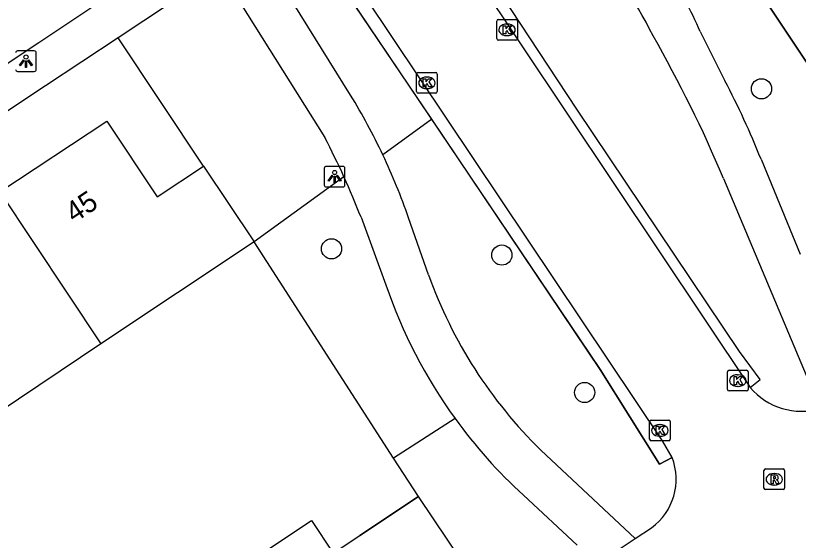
# Model space of a CAD drawing. Extents: x 158352 to 159489, y 383828 to 384597.
# Drawn here: x 158685.53 to 158723.41, y 384335.08 to 384360.5 of the extents above; entities that cross this region are included whole.
import ezdxf

# ---------------------------------------------------------------- set-up
doc = ezdxf.new("R2010")
doc.units = 0
for name, color, linetype in [('IMGEO_Boom', 7, 'Continuous'), ('IMGEO_Groenvoorziening', 7, 'Continuous'), ('IMGEO_Haag', 7, 'Continuous'), ('IMGEO_Kolk', 7, 'Continuous'), ('IMGEO_Lichtpunt', 7, 'Continuous'), ('IMGEO_Muur', 7, 'Continuous'), ('IMGEO_Pand', 7, 'Continuous'), ('IMGEO_Pand_nummerreeks', 7, 'Continuous'), ('IMGEO_Rijbaan_lokaal_open', 7, 'Continuous'), ('IMGEO_Rioolput', 7, 'Continuous'), ('IMGEO_Voetpad_gesloten', 7, 'Continuous'), ('IMGEO_Voetpad_open', 7, 'Continuous')]:
    doc.layers.add(name, color=color, linetype=linetype)

msp = doc.modelspace()

# ---------------------------------------------------------------- linework, layer by layer
at = {"layer": 'IMGEO_Boom'}
for centre in [(158721.624, 384356.956), (158700.816, 384349.204), (158709.059, 384348.902), (158713.066, 384342.244)]:
    msp.add_circle(centre, 0.489, dxfattribs=at)
at = {"layer": 'IMGEO_Groenvoorziening'}
for points in [[(158721.08, 384342.484), (158721.565, 384342.867), (158720.569, 384344.237), (158712.693, 384355.962), (158705.402, 384367.055), (158704.999, 384368.433), (158707.385, 384369.905), (158707.074, 384370.542)], [(158705.665, 384355.479), (158699.704, 384364.332), (158699.322, 384364.675), (158698.031, 384363.799), (158697.75, 384364.255)], [(158720.967, 384362.517), (158727.592, 384352.549), (158727.446, 384352.432), (158727.575, 384352.237)], [(158694.612, 384353.216), (158690.486, 384359.432)], [(158705.665, 384355.479), (158703.3, 384353.75)], [(158717.302, 384339.096), (158716.687, 384338.771), (158713.823, 384343.363), (158705.665, 384355.479)], [(158701.417, 384352.687), (158697.064, 384349.538)], [(158703.821, 384339.058), (158697.064, 384349.538)], [(158706.791, 384340.99), (158703.821, 384339.058)], [(158705.018, 384337.202), (158703.821, 384339.058)]]:
    msp.add_lwpolyline(points, dxfattribs=at)
at = {"layer": 'IMGEO_Haag'}
for points in [[(158705.57, 384365.721), (158721.08, 384342.484), (158721.565, 384342.867), (158720.569, 384344.237), (158712.693, 384355.962), (158705.402, 384367.055), (158704.999, 384368.433), (158707.385, 384369.905), (158707.074, 384370.542)], [(158699.316, 384365.295), (158697.75, 384364.255), (158698.031, 384363.799), (158699.322, 384364.675), (158699.704, 384364.332), (158713.823, 384343.363), (158716.687, 384338.771), (158717.302, 384339.096), (158716.829, 384339.908), (158701.145, 384363.368)]]:
    msp.add_lwpolyline(points, dxfattribs=at)
at = {"layer": 'IMGEO_Kolk'}
for p, q in [((158708.808, 384359.387), (158708.808, 384360.239)), ((158708.883, 384360.313), (158709.735, 384360.313)), ((158709.296, 384360.093), (158709.321, 384360.093)), ((158709.809, 384360.239), (158709.809, 384359.387)), ((158709.735, 384359.313), (158708.883, 384359.313)), ((158709.319, 384359.533), (158709.294, 384359.533)), ((158704.933, 384356.817), (158704.933, 384357.669)), ((158705.008, 384357.743), (158705.86, 384357.743)), ((158705.421, 384357.523), (158705.446, 384357.523)), ((158705.934, 384357.669), (158705.934, 384356.817)), ((158705.86, 384356.743), (158705.008, 384356.743)), ((158705.444, 384356.963), (158705.419, 384356.963)), ((158719.98, 384342.397), (158719.98, 384343.249)), ((158720.055, 384343.323), (158720.907, 384343.323)), ((158720.468, 384343.103), (158720.493, 384343.103)), ((158720.981, 384343.249), (158720.981, 384342.397)), ((158720.907, 384342.323), (158720.055, 384342.323)), ((158720.491, 384342.543), (158720.466, 384342.543)), ((158716.207, 384339.982), (158716.207, 384340.834)), ((158716.282, 384340.908), (158717.134, 384340.908)), ((158717.208, 384340.834), (158717.208, 384339.982)), ((158716.695, 384340.688), (158716.72, 384340.688)), ((158716.718, 384340.128), (158716.693, 384340.128)), ((158717.134, 384339.908), (158716.282, 384339.908))]:
    msp.add_line(p, q, dxfattribs=at)
for points in [[(158708.808, 384359.387), (158708.808, 384360.239)], [(158708.883, 384360.313), (158709.735, 384360.313)], [(158709.809, 384360.239), (158709.809, 384359.387)], [(158709.129, 384360.013), (158709.252, 384360.013), (158709.252, 384359.862), (158709.382, 384360.013), (158709.546, 384360.013), (158709.4, 384359.862), (158709.553, 384359.613), (158709.401, 384359.613), (158709.316, 384359.777), (158709.252, 384359.71), (158709.252, 384359.613), (158709.129, 384359.613), (158709.129, 384360.013)], [(158709.735, 384359.313), (158708.883, 384359.313)], [(158704.933, 384356.817), (158704.933, 384357.669)], [(158705.008, 384357.743), (158705.86, 384357.743)], [(158705.254, 384357.443), (158705.377, 384357.443), (158705.377, 384357.292), (158705.507, 384357.443), (158705.671, 384357.443), (158705.525, 384357.292), (158705.678, 384357.043), (158705.526, 384357.043), (158705.441, 384357.207), (158705.377, 384357.14), (158705.377, 384357.043), (158705.254, 384357.043), (158705.254, 384357.443)], [(158705.934, 384357.669), (158705.934, 384356.817)], [(158705.86, 384356.743), (158705.008, 384356.743)], [(158719.98, 384342.397), (158719.98, 384343.249)], [(158720.055, 384343.323), (158720.907, 384343.323)], [(158720.301, 384343.023), (158720.424, 384343.023), (158720.424, 384342.872), (158720.554, 384343.023), (158720.718, 384343.023), (158720.572, 384342.872), (158720.725, 384342.623), (158720.573, 384342.623), (158720.488, 384342.787), (158720.424, 384342.72), (158720.424, 384342.623), (158720.301, 384342.623), (158720.301, 384343.023)], [(158720.981, 384343.249), (158720.981, 384342.397)], [(158720.907, 384342.323), (158720.055, 384342.323)], [(158716.207, 384339.982), (158716.207, 384340.834)], [(158716.282, 384340.908), (158717.134, 384340.908)], [(158717.208, 384340.834), (158717.208, 384339.982)], [(158716.528, 384340.608), (158716.651, 384340.608), (158716.651, 384340.457), (158716.781, 384340.608), (158716.945, 384340.608), (158716.799, 384340.457), (158716.952, 384340.208), (158716.8, 384340.208), (158716.715, 384340.372), (158716.651, 384340.305), (158716.651, 384340.208), (158716.528, 384340.208), (158716.528, 384340.608)], [(158717.134, 384339.908), (158716.282, 384339.908)]]:
    msp.add_lwpolyline(points, dxfattribs=at)
for centre, start, end in [((158708.885, 384360.237), 91.552, 178.448), ((158708.885, 384360.237), 91.552, 178.448), ((158709.733, 384360.237), 1.552, 88.448), ((158709.733, 384360.237), 1.552, 88.448), ((158708.885, 384359.389), 181.552, 268.448), ((158708.885, 384359.389), 181.552, 268.448), ((158709.733, 384359.389), 271.552, 358.448), ((158709.733, 384359.389), 271.552, 358.448), ((158705.01, 384357.667), 91.552, 178.448), ((158705.01, 384357.667), 91.552, 178.448), ((158705.858, 384357.667), 1.552, 88.448), ((158705.858, 384357.667), 1.552, 88.448), ((158705.01, 384356.819), 181.552, 268.448), ((158705.01, 384356.819), 181.552, 268.448), ((158705.858, 384356.819), 271.552, 358.448), ((158705.858, 384356.819), 271.552, 358.448), ((158720.057, 384343.247), 91.552, 178.448), ((158720.057, 384343.247), 91.552, 178.448), ((158720.905, 384343.247), 1.552, 88.448), ((158720.905, 384343.247), 1.552, 88.448), ((158720.057, 384342.399), 181.552, 268.448), ((158720.057, 384342.399), 181.552, 268.448), ((158720.905, 384342.399), 271.552, 358.448), ((158720.905, 384342.399), 271.552, 358.448), ((158716.284, 384340.832), 91.552, 178.448), ((158716.284, 384340.832), 91.552, 178.448), ((158717.132, 384340.832), 1.552, 88.448), ((158717.132, 384340.832), 1.552, 88.448), ((158716.284, 384339.984), 181.552, 268.448), ((158716.284, 384339.984), 181.552, 268.448), ((158717.132, 384339.984), 271.552, 358.448), ((158717.132, 384339.984), 271.552, 358.448)]:
    msp.add_arc(centre, 0.0765, start, end, dxfattribs=at)
for centre, major_axis, ratio, start_param, end_param in [((158709.295, 384359.813), (-0.387, 0.002), 0.722429, 4.712389, 7.853982), ((158709.32, 384359.813), (-0.39, 0.002), 0.717154, 1.570796, 4.712389), ((158705.42, 384357.243), (-0.387, 0.002), 0.722429, 4.712389, 7.853982), ((158705.445, 384357.243), (-0.39, 0.002), 0.717154, 1.570796, 4.712389), ((158720.467, 384342.823), (-0.387, 0.002), 0.722429, 4.712389, 7.853982), ((158720.492, 384342.823), (-0.39, 0.002), 0.717154, 1.570796, 4.712389), ((158716.694, 384340.408), (-0.387, 0.002), 0.722429, 4.712389, 7.853982), ((158716.719, 384340.408), (-0.39, 0.002), 0.717154, 1.570796, 4.712389)]:
    msp.add_ellipse(centre, major_axis=major_axis, ratio=ratio, start_param=start_param, end_param=end_param, dxfattribs=at)
at = {"layer": 'IMGEO_Lichtpunt'}
for p, q in [((158686.428, 384358.791), (158685.62, 384358.791)), ((158686.428, 384358.791), (158685.62, 384358.791)), ((158686.522, 384357.889), (158686.522, 384358.696)), ((158686.522, 384357.889), (158686.522, 384358.696)), ((158685.62, 384357.795), (158686.428, 384357.795)), ((158685.62, 384357.795), (158686.428, 384357.795)), ((158700.465, 384353.102), (158700.465, 384352.295)), ((158700.465, 384353.102), (158700.465, 384352.295)), ((158701.367, 384353.197), (158700.559, 384353.197)), ((158701.367, 384353.197), (158700.559, 384353.197)), ((158701.461, 384352.295), (158701.461, 384353.102)), ((158701.461, 384352.295), (158701.461, 384353.102)), ((158700.559, 384352.201), (158701.367, 384352.201)), ((158700.559, 384352.201), (158701.367, 384352.201))]:
    msp.add_line(p, q, dxfattribs=at)
for points in [[(158685.9, 384358.36), (158685.939, 384358.332), (158685.751, 384358.07), (158685.713, 384358.097), (158685.9, 384358.36)], [(158686.002, 384358.312), (158686.049, 384358.312), (158686.049, 384357.99), (158686.002, 384357.99), (158686.002, 384358.312)], [(158686.112, 384358.332), (158686.15, 384358.359), (158686.337, 384358.097), (158686.298, 384358.069), (158686.112, 384358.332)], [(158700.839, 384352.766), (158700.878, 384352.738), (158700.69, 384352.476), (158700.652, 384352.503), (158700.839, 384352.766)], [(158700.941, 384352.718), (158700.988, 384352.718), (158700.988, 384352.396), (158700.941, 384352.396), (158700.941, 384352.718)], [(158701.051, 384352.738), (158701.089, 384352.765), (158701.276, 384352.503), (158701.237, 384352.475), (158701.051, 384352.738)]]:
    msp.add_lwpolyline(points, dxfattribs=at)
for centre in [(158686.025, 384358.494), (158700.964, 384352.9)]:
    msp.add_circle(centre, 0.0994, dxfattribs=at)
for centre, start, end in [((158685.62, 384358.696), 90, 180), ((158685.62, 384358.696), 90, 180), ((158686.428, 384358.696), 0, 90), ((158686.428, 384358.696), 0, 90), ((158685.62, 384357.889), 180, 270), ((158685.62, 384357.889), 180, 270), ((158686.428, 384357.889), 270, 0), ((158686.428, 384357.889), 270, 360), ((158700.559, 384353.102), 90, 180), ((158700.559, 384353.102), 90, 180), ((158701.367, 384353.102), 0, 90), ((158701.367, 384353.102), 0, 90), ((158700.559, 384352.295), 180, 270), ((158700.559, 384352.295), 180, 270), ((158701.367, 384352.295), 270, 0), ((158701.367, 384352.295), 270, 360)]:
    msp.add_arc(centre, 0.0946, start, end, dxfattribs=at)
at = {"layer": 'IMGEO_Muur'}
for points in [[(158727.575, 384352.237), (158727.446, 384352.432), (158727.592, 384352.549), (158720.967, 384362.517)], [(158705.018, 384337.202), (158703.821, 384339.058), (158697.064, 384349.538)], [(158705.018, 384337.202), (158702.178, 384335.311)], [(158710.956, 384333.528), (158708.555, 384331.94), (158705.018, 384337.202)]]:
    msp.add_lwpolyline(points, dxfattribs=at)
at = {"layer": 'IMGEO_Pand'}
for points in [[(158684.738, 384351.963), (158689.934, 384355.386), (158692.374, 384351.725), (158694.612, 384353.216)], [(158694.612, 384353.216), (158697.064, 384349.538)], [(158684.738, 384351.963), (158689.651, 384344.598)], [(158697.064, 384349.538), (158689.651, 384344.598)], [(158689.651, 384344.598), (158684.664, 384341.256)], [(158696.723, 384333.957), (158699.844, 384336.043), (158700.9, 384334.463)]]:
    msp.add_lwpolyline(points, dxfattribs=at)
at = {"layer": 'IMGEO_Rijbaan_lokaal_open'}
for points in [[(158705.57, 384365.721), (158721.08, 384342.484)], [(158717.302, 384339.096), (158716.829, 384339.908), (158701.145, 384363.368)], [(158715.512, 384335.167), (158716.309, 384335.695)], [(158713.671, 384333.948), (158715.512, 384335.167)]]:
    msp.add_lwpolyline(points, dxfattribs=at)
for centre, radius, start, end in [((158723.552, 384344.574), 3.237, 220.2193, 286.466), ((158714.571, 384338.048), 2.925, 306.449, 20.9982)]:
    msp.add_arc(centre, radius, start, end, dxfattribs=at)
at = {"layer": 'IMGEO_Rioolput'}
for p, q in [((158721.745, 384337.615), (158721.745, 384338.467)), ((158721.82, 384338.541), (158722.672, 384338.541)), ((158722.746, 384338.467), (158722.746, 384337.615)), ((158722.233, 384338.321), (158722.258, 384338.321)), ((158722.256, 384337.761), (158722.231, 384337.761)), ((158722.672, 384337.541), (158721.82, 384337.541))]:
    msp.add_line(p, q, dxfattribs=at)
for points in [[(158721.745, 384337.615), (158721.745, 384338.467)], [(158721.82, 384338.541), (158722.672, 384338.541)], [(158722.746, 384338.467), (158722.746, 384337.615)], [(158722.334, 384338.239), (158722.082, 384338.241), (158722.082, 384337.841)], [(158722.26, 384338.16), (158722.206, 384338.16), (158722.206, 384338.079)], [(158722.082, 384337.841), (158722.206, 384337.841), (158722.206, 384338.003), (158722.217, 384338.003)], [(158722.206, 384338.079), (158722.258, 384338.079)], [(158722.264, 384337.974), (158722.335, 384337.841), (158722.475, 384337.841), (158722.41, 384337.967)], [(158722.672, 384337.541), (158721.82, 384337.541)]]:
    msp.add_lwpolyline(points, dxfattribs=at)
for centre, radius, start, end in [((158721.822, 384338.465), 0.0765, 91.552, 178.448), ((158721.822, 384338.465), 0.0765, 91.552, 178.448), ((158722.67, 384338.465), 0.0765, 1.552, 88.448), ((158722.67, 384338.465), 0.0765, 1.552, 88.448), ((158722.242, 384338.268), 0.19, 274.7715, 282.9687), ((158722.266, 384338.064), 0.0964, 77.0061, 93.1865), ((158722.28, 384338.121), 0.0378, 276.6634, 79.6772), ((158722.333, 384338.129), 0.109, 350.3612, 89.416), ((158722.331, 384338.129), 0.112, 277.5842, 350.9817), ((158722.216, 384337.95), 0.0533, 26.0293, 88.6989), ((158722.315, 384337.914), 0.108, 29.5134, 73.7905), ((158721.822, 384337.617), 0.0765, 181.552, 268.448), ((158721.822, 384337.617), 0.0765, 181.552, 268.448), ((158722.67, 384337.617), 0.0765, 271.552, 358.448), ((158722.67, 384337.617), 0.0765, 271.552, 358.448)]:
    msp.add_arc(centre, radius, start, end, dxfattribs=at)
for centre, major_axis, ratio, start_param, end_param in [((158722.232, 384338.041), (-0.387, 0.002), 0.722429, 4.712389, 7.853982), ((158722.257, 384338.041), (-0.39, 0.002), 0.717154, 1.570796, 4.712389)]:
    msp.add_ellipse(centre, major_axis=major_axis, ratio=ratio, start_param=start_param, end_param=end_param, dxfattribs=at)
at = {"layer": 'IMGEO_Voetpad_gesloten'}
for points in [[(158701.74, 384356.644), (158697.233, 384363.912)], [(158695.416, 384362.705), (158700.493, 384354.599)], [(158718.661, 384359.724), (158719.851, 384357.347)], [(158721.602, 384353.545), (158723.502, 384348.951)], [(158719.789, 384352.617), (158724.469, 384341.47)], [(158702.242, 384350.73), (158703.45, 384347.456)], [(158705.51, 384347.945), (158704.548, 384350.708)], [(158715.512, 384335.167), (158710.948, 384339.452)], [(158712.697, 384334.843), (158710.101, 384337.266)]]:
    msp.add_lwpolyline(points, dxfattribs=at)
for centre, radius, start, end in [((158699.629, 384351.337), 18.641, 26.0267, 44.4344), ((158703.138, 384353.15), 16.857, 22.9533, 34.2649), ((158659, 384326.876), 66.015, 22.95031, 29.63378), ((158684.902, 384338.947), 39.497, 21.6908, 27.7658), ((158674.842, 384340.277), 31.487, 25.3341, 31.3194), ((158663.128, 384335.363), 42.025, 24.345, 27.2405), ((158674.921, 384340.33), 31.392, 19.3042, 25.3082), ((158663.788, 384335.672), 41.297, 21.3851, 24.332), ((158726.651, 384355.494), 22.448, 199.6503, 225.612), ((158726.772, 384355.41), 24.641, 198.8327, 215.8184), ((158726.797, 384355.439), 24.678, 215.8379, 227.4254)]:
    msp.add_arc(centre, radius, start, end, dxfattribs=at)
at = {"layer": 'IMGEO_Voetpad_open'}
for points in [[(158647.518, 384335.038), (158648.374, 384333.728), (158686.654, 384359.199), (158690.04, 384361.478), (158689.167, 384362.842)], [(158695.416, 384362.705), (158690.486, 384359.432)], [(158690.486, 384359.432), (158686.972, 384357.1), (158650.515, 384332.795), (158646.346, 384330.011)], [(158700.9, 384334.463), (158702.178, 384335.311), (158705.018, 384337.202)], [(158710.956, 384333.528), (158708.555, 384331.94), (158705.018, 384337.202)]]:
    msp.add_lwpolyline(points, dxfattribs=at)

# ---------------------------------------------------------------- texts
at = {"layer": 'IMGEO_Pand_nummerreeks'}
msp.add_text('45', height=1, rotation=33.5712, dxfattribs=at).set_placement((158688.357, 384350.429))

doc.saveas('drawing.dxf')
